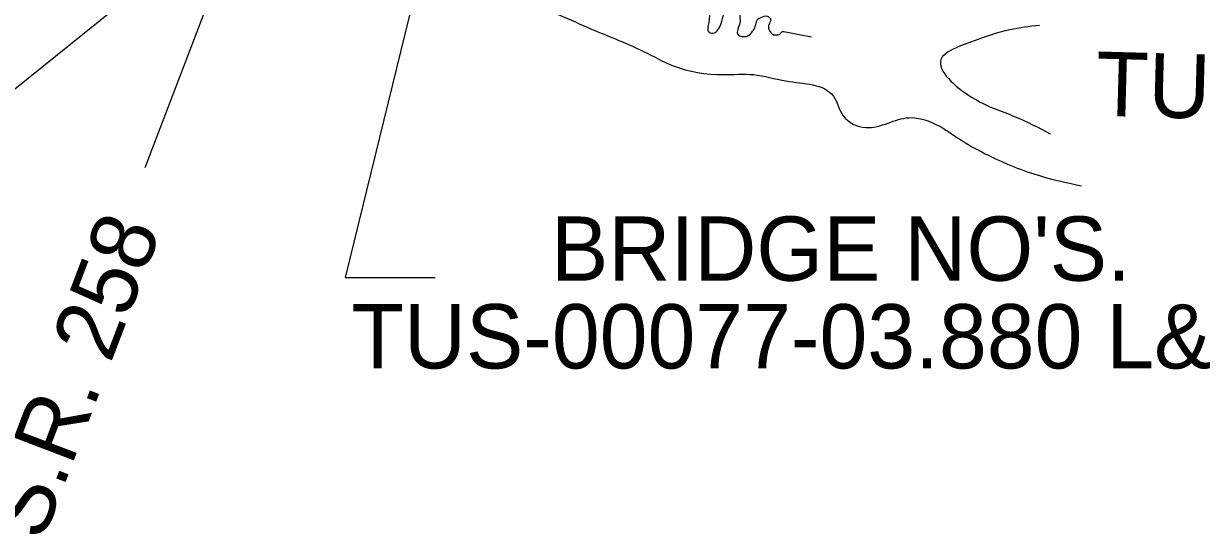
# Model space of a CAD drawing. Extents: x 0 to 34000, y 0 to 22000.
# Drawn here: x 25424 to 27999, y 4486 to 5602 of the extents above; entities that cross this region are included whole.
import ezdxf

# ---------------------------------------------------------------- set-up
doc = ezdxf.new("R2010")
doc.units = 0
doc.layers.add('Default', color=7, linetype='Continuous')
doc.layers.add('GE_P_CL_100', color=7, linetype='Continuous')

msp = doc.modelspace()

# ---------------------------------------------------------------- linework, layer by layer
at = {"layer": 'Default'}
for p, q in [((25689.3, 5289.1), (25974.1, 6036.7)), ((27080.3, 5585.4), (27140.8, 5573.4))]:
    msp.add_line(p, q, dxfattribs=at)
for points in [[(26362.9, 5795.7), (26398, 5735.2), (26452.7, 5684.5), (26538.5, 5639.6), (26583.4, 5624), (26651.7, 5594.7), (26774.7, 5542), (26839.1, 5510.8), (26948.4, 5491.3), (27014.7, 5491.3), (27085, 5477.6), (27188.4, 5444.4), (27209.9, 5401.5), (27258.7, 5376.1), (27307.5, 5385.9), (27352.4, 5397.6), (27420.7, 5378.1), (27469.5, 5346.9), (27526.1, 5315.6), (27639.3, 5270.7), (27729, 5249.3)], [(26886, 5623.9), (26888.3, 5624.2), (26890.3, 5627.8), (26894.4, 5634.3), (26901.9, 5639.4), (26910.5, 5640.9), (26914.1, 5637.4), (26917.6, 5630.8), (26918.6, 5620.2), (26917.1, 5608), (26915.1, 5596.4), (26915.6, 5585.8), (26926.2, 5581.3), (26936.8, 5588.8), (26943.9, 5602.5), (26949.5, 5624.2), (26955.5, 5634.3), (26963.1, 5638.4), (26980.8, 5632.3), (26984.3, 5619.2), (26984.8, 5604), (26979.8, 5589.8), (26979.8, 5579.2), (26989.9, 5574.7), (27000.5, 5575.2), (27012.1, 5585.8), (27018.2, 5595.9), (27023.2, 5611.6), (27030.8, 5616.1), (27044.5, 5618.7), (27051, 5613.6), (27049, 5603), (27047, 5592.4), (27051.5, 5583.8), (27055.6, 5579.2), (27064.2, 5577.7), (27071.8, 5579.7), (27076.3, 5584.3), (27080.3, 5585.4)], [(27637.3, 5598.6), (27572.9, 5588.9), (27485.1, 5561.5), (27422.6, 5524.5), (27489, 5442.5), (27584.6, 5399.6), (27660.7, 5362.5)]]:
    msp.add_spline(points, degree=3, dxfattribs=at)
at = {"layer": 'GE_P_CL_100'}
for p, q in [((26322.5, 5854.6), (26124.4, 5049.7)), ((25802.5, 5779.9), (25351.3, 5416.6)), ((26124.4, 5049.7), (26320.9, 5049.7))]:
    msp.add_line(p, q, dxfattribs=at)

# ---------------------------------------------------------------- texts
for s, rotation, p in [('TUSCARAWAS RIVER', 358.4259, (27758.4, 5401.9)), ('S.R. 258', 69.1419, (25465.2, 4471.6))]:
    msp.add_text(s, height=140, rotation=rotation, dxfattribs=at).set_placement(p)
for s, p in [("BRIDGE NO'S.", (26573.2, 5042.5)), ('TUS-00077-03.880 L&R', (26138.4, 4851.5))]:
    msp.add_text(s, height=140, dxfattribs=at).set_placement(p)

doc.saveas('drawing.dxf')
